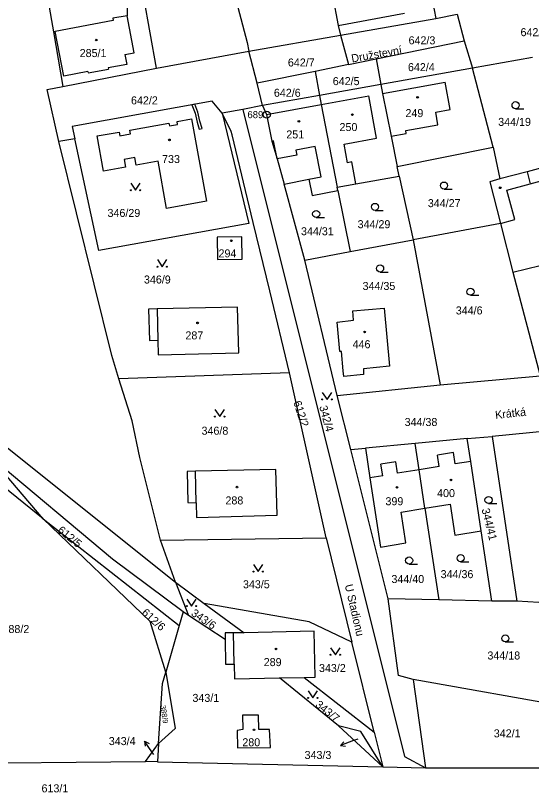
# Model space of a CAD drawing. Extents: x -758582 to -751794, y -998770 to -994350.
# Drawn here: x -756048.6 to -755939, y -995504.9 to -995339.9 of the extents above; entities that cross this region are included whole.
import ezdxf

# ---------------------------------------------------------------- set-up
doc = ezdxf.new("R2010")
doc.units = 0
for name, color, linetype in [('Hranice parcel', 7, 'Continuous'), ('Parcelní čísla', 7, 'Continuous'), ('Pop  PČ popisy', 7, 'Continuous'), ('Vnitřní kresba', 7, 'Continuous'), ('Věcná břemena k části', 7, 'Continuous'), ('Značky bodu BP', 7, 'Continuous'), ('Značky budov', 7, 'Continuous'), ('Značky kultur', 7, 'Continuous')]:
    doc.layers.add(name, color=color, linetype=linetype)

msp = doc.modelspace()

# ---------------------------------------------------------------- linework, layer by layer
at = {"layer": 'Hranice parcel'}
for p, q in [((-756018.71, -995351.04), (-756025.08, -995315.04)), ((-755959.34, -995340.51), (-755954.86, -995339.59)), ((-755954.86, -995339.59), (-755953.31, -995345.27)), ((-755979.58, -995344.08), (-755959.34, -995340.51)), ((-756040.6, -995343.32), (-756038.56, -995354.92)), ((-755999.06, -995347.44), (-755979.58, -995344.08)), ((-755979.58, -995344.08), (-755977.9, -995350.29)), ((-755972.03, -995349.09), (-755953.31, -995345.27)), ((-755953.31, -995345.27), (-755951.55, -995351.05)), ((-756018.71, -995351.04), (-755999.06, -995347.44)), ((-755997.28, -995354.25), (-755999.06, -995347.44)), ((-755977.9, -995350.29), (-755972.03, -995349.09)), ((-755972.03, -995349.09), (-755971.01, -995354.53)), ((-755938.83, -995348.79), (-755951.55, -995351.05)), ((-756038.56, -995354.92), (-756018.71, -995351.04)), ((-755985, -995351.74), (-755997.28, -995354.25)), ((-755977.9, -995350.29), (-755985, -995351.74)), ((-755985, -995351.74), (-755984.08, -995356.86)), ((-755951.55, -995351.05), (-755971.01, -995354.53)), ((-755947.19, -995367.83), (-755951.55, -995351.05)), ((-755996.16, -995359.02), (-755997.28, -995354.25)), ((-755971.01, -995354.53), (-755984.08, -995356.86)), ((-756006.88, -995358.06), (-756036.64, -995363.44)), ((-756004.76, -995360.64), (-756006.88, -995358.06)), ((-755984.08, -995356.86), (-755996.16, -995359.02)), ((-756000.35, -995359.81), (-756004.76, -995360.64)), ((-755996.16, -995359.02), (-756000.35, -995359.81)), ((-756004.76, -995360.64), (-755999.11, -995384.02)), ((-756036.64, -995363.44), (-756036.07, -995366.05)), ((-756036.07, -995366.05), (-756039.42, -995366.63)), ((-756030.95, -995389.82), (-756036.07, -995366.05)), ((-755967.56, -995371.96), (-755947.19, -995367.83)), ((-755947.19, -995367.83), (-755945.73, -995374.6)), ((-755967.16, -995373.98), (-755967.56, -995371.96)), ((-755967.16, -995373.98), (-755964.2, -995387.52)), ((-755987.18, -995391.82), (-755991.6, -995375.68)), ((-755980.19, -995377.02), (-755980.32, -995376.37)), ((-755980.19, -995377.02), (-755977.54, -995390.02)), ((-755999.11, -995384.02), (-756030.95, -995389.82)), ((-755945.62, -995384.05), (-755964.2, -995387.52)), ((-755945.62, -995384.05), (-755942.97, -995394.4)), ((-755977.54, -995390.02), (-755964.2, -995387.52)), ((-755964.2, -995387.52), (-755958.43, -995418.29)), ((-755987.18, -995391.82), (-755977.54, -995390.02)), ((-755980.31, -995420.59), (-755987.18, -995391.82)), ((-755942.97, -995394.4), (-755937.22, -995416.42)), ((-755990.43, -995415.78), (-756026.67, -995417.07)), ((-755982.69, -995450.85), (-755990.43, -995415.78)), ((-755958.43, -995418.29), (-755937.22, -995416.42)), ((-755980.31, -995420.59), (-755958.43, -995418.29)), ((-756064.11, -995420.68), (-756014.69, -995460.26)), ((-755977.43, -995432.09), (-755980.31, -995420.59)), ((-755929.72, -995427.54), (-755947.39, -995429.29)), ((-756042.77, -995446.79), (-756066.24, -995427.83)), ((-755952.69, -995429.73), (-755947.39, -995429.29)), ((-755947.39, -995429.29), (-755942.14, -995464.27)), ((-755963.78, -995430.8), (-755974.31, -995431.81)), ((-755952.69, -995429.73), (-755963.78, -995430.8)), ((-755977.43, -995432.09), (-755974.31, -995431.81)), ((-755969.45, -995463.77), (-755977.43, -995432.09)), ((-756042.77, -995446.79), (-756053.98, -995433.7)), ((-755961.69, -995444.53), (-755958.72, -995464.02)), ((-756042.77, -995446.79), (-756013.89, -995469.44)), ((-755947.43, -995464.28), (-755949.71, -995449.32)), ((-756017.87, -995451.33), (-755982.69, -995450.85)), ((-756014.69, -995460.26), (-756017.87, -995451.33)), ((-755982.69, -995450.85), (-755977.2, -995472.97)), ((-756014.69, -995460.26), (-756008.57, -995464.75)), ((-756014.69, -995460.26), (-756011.88, -995467.33)), ((-755958.72, -995464.02), (-755969.45, -995463.77)), ((-756008.57, -995464.75), (-756000.08, -995470.97)), ((-755947.43, -995464.28), (-755958.72, -995464.02)), ((-755942.14, -995464.27), (-755947.43, -995464.28)), ((-755924.21, -995465.35), (-755942.14, -995464.27)), ((-756013.06, -995466.56), (-756013.89, -995469.44)), ((-756011.88, -995467.33), (-756013.06, -995466.56)), ((-756004.08, -995472.41), (-756011.88, -995467.33)), ((-756013.89, -995469.44), (-756016.74, -995479.39)), ((-755972.46, -995492.09), (-755977.2, -995472.97)), ((-755992.54, -995480.58), (-755987.33, -995480.49)), ((-755980.04, -995490.76), (-755992.54, -995480.58)), ((-755987.33, -995480.49), (-755972.46, -995492.09)), ((-755964.16, -995480.95), (-755961.54, -995499.7)), ((-755970.63, -995499.45), (-755980.04, -995490.76)), ((-755972.46, -995492.09), (-755970.63, -995499.45)), ((-756021.03, -995498.34), (-756018.3, -995494.51)), ((-756018.3, -995494.51), (-756018.48, -995498.41)), ((-756018.48, -995498.41), (-756021.03, -995498.34)), ((-756018.48, -995498.41), (-755970.63, -995499.45)), ((-755970.63, -995499.45), (-755961.54, -995499.7)), ((-755961.54, -995499.7), (-755922.63, -995499.63))]:
    msp.add_line(p, q, dxfattribs=at)
for points in [[(-756029.41, -995294.31), (-756049.85, -995298.02), (-756045.34, -995316.28), (-756040.6, -995343.32)], [(-756007.01, -995316.86), (-755999.42, -995345.57), (-755999.06, -995347.44)], [(-755983.21, -995325.04), (-755981.28, -995335.57), (-755980.1, -995341.96), (-755979.58, -995344.08)], [(-755962.33, -995324.06), (-755960.86, -995332.14), (-755959.68, -995338.64), (-755959.34, -995340.51)], [(-756024.95, -995329.96), (-756024.91, -995339.91), (-756027.96, -995340.47), (-756027.87, -995340.96), (-756040.22, -995343.25), (-756040.6, -995343.32)], [(-756039.42, -995366.63), (-756041.92, -995355.6), (-756038.56, -995354.92)], [(-755971.01, -995354.53), (-755970.67, -995356.42), (-755968.86, -995365.49), (-755967.56, -995371.96)], [(-755984.08, -995356.86), (-755983.73, -995358.8), (-755980.32, -995376.37)], [(-756000.35, -995359.81), (-755966.03, -995497.26), (-755961.54, -995499.7)], [(-755996.16, -995359.02), (-755995.31, -995360.91), (-755994.18, -995366.59), (-755993.06, -995370.34), (-755991.6, -995375.68)], [(-755990.43, -995415.78), (-755994.59, -995398.38), (-755998.15, -995383.85), (-756002.6, -995365.24), (-756002.84, -995364.5), (-756004.76, -995360.64)], [(-756026.62, -995364.62), (-756026.47, -995365.44), (-756024.22, -995365.02), (-756024.37, -995364.21), (-756016.09, -995362.71), (-756015.96, -995363.33), (-756014.24, -995363.04), (-756014.34, -995362.4), (-756011.25, -995361.83), (-756008.1, -995379.31), (-756016.56, -995380.84), (-756018.37, -995370.82), (-756023.03, -995371.67), (-756023.33, -995370.03), (-756025.57, -995370.45), (-756025.27, -995372.06), (-756029.93, -995372.92), (-756031.27, -995365.46), (-756026.62, -995364.62)], [(-756026.67, -995417.07), (-756028.21, -995412.11), (-756039.42, -995366.63)], [(-755933.12, -995371.25), (-755934.52, -995371.62), (-755939.98, -995373.07), (-755945.73, -995374.6)], [(-755991.6, -995375.68), (-755986.35, -995374.64), (-755985.66, -995378.1), (-755980.19, -995377.02)], [(-755980.32, -995376.37), (-755976.38, -995375.65), (-755967.16, -995373.98)], [(-755945.73, -995374.6), (-755947.89, -995375.18), (-755945.62, -995384.05)], [(-756000.51, -995391.6), (-756000.59, -995386.87), (-756005.84, -995386.94), (-756005.75, -995391.72), (-756000.51, -995391.6)], [(-755942.97, -995394.4), (-755937.2, -995392.95), (-755932.45, -995391.73)], [(-756001.2, -995411.52), (-756001.47, -995401.81), (-756018.57, -995402.2), (-756020.37, -995402.24), (-756020.21, -995408.89), (-756018.41, -995408.85), (-756018.33, -995411.94), (-756001.2, -995411.52)], [(-755970.35, -995402.03), (-755969.19, -995414.38), (-755974.7, -995414.91), (-755974.69, -995416.15), (-755978.93, -995416.55), (-755979.02, -995415.38), (-755979.37, -995411.22), (-755979.77, -995411.25), (-755980.34, -995405.02), (-755976.84, -995404.59), (-755976.99, -995402.63), (-755970.35, -995402.03)], [(-756017.87, -995451.33), (-756022.21, -995433.78), (-756023.9, -995425.98), (-756026.67, -995417.07)], [(-755961.69, -995444.53), (-755962.93, -995436.38), (-755963.78, -995430.8)], [(-755949.71, -995449.32), (-755951.95, -995434.6), (-755952.69, -995429.73)], [(-755974.31, -995431.81), (-755973.37, -995438.07), (-755971.12, -995452.8), (-755965.7, -995451.92), (-755966.7, -995445.34), (-755961.69, -995444.53)], [(-756013.06, -995466.56), (-756028.01, -995455.35), (-756053.98, -995433.7)], [(-756010.39, -995436.68), (-756012.18, -995436.72), (-756012.06, -995443.34), (-756010.27, -995443.36), (-756010.2, -995446.48), (-755993.08, -995446.03), (-755993.34, -995436.31), (-756010.39, -995436.68)], [(-755961.69, -995444.53), (-755956.32, -995443.66), (-755955.32, -995450.23), (-755949.71, -995449.32)], [(-756016.74, -995479.39), (-756020.05, -995468.59), (-756042.77, -995446.79)], [(-755964.16, -995480.95), (-755967.26, -995480.08), (-755969.45, -995463.77)], [(-755977.2, -995472.97), (-755986.25, -995468.66), (-756008.57, -995464.75)], [(-756000.08, -995470.97), (-756002.31, -995471.02), (-756004.08, -995471.04), (-756004.08, -995472.41)], [(-755987.33, -995480.49), (-755984.99, -995480.45), (-755985.17, -995470.64), (-756000.08, -995470.97)], [(-756004.08, -995472.41), (-756004.07, -995477.65), (-756002.17, -995477.65), (-756002.11, -995480.79), (-755992.54, -995480.58)], [(-756016.74, -995479.39), (-756014.74, -995491.35), (-756018.3, -995494.51)], [(-756018.3, -995494.51), (-756017.43, -995481.8), (-756016.74, -995479.39)], [(-755924.33, -995487.02), (-755930.67, -995486.87), (-755964.16, -995480.95)], [(-756000.42, -995488.5), (-756000.36, -995491.54), (-756001.54, -995491.73), (-756001.46, -995495.43), (-755994.49, -995495.33), (-755994.7, -995491.57), (-755996.98, -995491.51), (-755997.01, -995488.47), (-756000.42, -995488.5)], [(-755970.63, -995499.45), (-755975.29, -995491.93), (-755980.04, -995490.76)], [(-756077.08, -995500.54), (-756065.33, -995498.79), (-756021.03, -995498.34)]]:
    msp.add_lwpolyline(points, dxfattribs=at)
at = {"layer": 'Pop  PČ popisy'}
for p, q in [((-755975.95, -995493.57), (-755976.83, -995493.9)), ((-756019.54, -995496.48), (-756021.22, -995493.99)), ((-756021.22, -995493.99), (-756020.24, -995494.54)), ((-756021.22, -995493.99), (-756021.07, -995495.1)), ((-755976.83, -995493.9), (-755979.63, -995494.97)), ((-755979.63, -995494.97), (-755978.88, -995494.15)), ((-755979.63, -995494.97), (-755978.52, -995495.08)), ((-756019.28, -995496.85), (-756019.54, -995496.48))]:
    msp.add_line(p, q, dxfattribs=at)
at = {"layer": 'Vnitřní kresba'}
for p, q in [((-756023.47, -995347.78), (-756024.91, -995339.91)), ((-755980.1, -995341.96), (-755966.03, -995339.37)), ((-756038.41, -995352.73), (-756040.22, -995343.25)), ((-756025.41, -995348.13), (-756023.47, -995347.78)), ((-756025.41, -995348.13), (-756025.02, -995350.26)), ((-756033.24, -995352.07), (-756028.87, -995351.25)), ((-756025.02, -995350.26), (-756028.93, -995350.98)), ((-756028.93, -995350.98), (-756028.87, -995351.25)), ((-756033.3, -995351.79), (-756038.41, -995352.73)), ((-756033.3, -995351.79), (-756033.24, -995352.07)), ((-755970.67, -995356.42), (-755957.39, -995354.01)), ((-755956.33, -995359.86), (-755957.39, -995354.01)), ((-755983.73, -995358.8), (-755973.59, -995356.95)), ((-755971.95, -995365.95), (-755973.59, -995356.95)), ((-755995.31, -995360.91), (-755983.73, -995358.8)), ((-755959.38, -995360.42), (-755956.33, -995359.86)), ((-755958.9, -995363.07), (-755959.38, -995360.42)), ((-755965.73, -995364.31), (-755958.9, -995363.07)), ((-755968.86, -995365.49), (-755965.63, -995364.9)), ((-755965.63, -995364.9), (-755965.73, -995364.31)), ((-755993.82, -995366.52), (-755994.18, -995366.59)), ((-755993.06, -995370.34), (-755993.82, -995366.52)), ((-755978.84, -995367.21), (-755971.95, -995365.95)), ((-755985.01, -995367.68), (-755989.12, -995368.49)), ((-755983.74, -995374.12), (-755985.01, -995367.68)), ((-755978.12, -995371.14), (-755978.84, -995367.21)), ((-755988.92, -995369.52), (-755993.06, -995370.34)), ((-755989.12, -995368.49), (-755988.92, -995369.52)), ((-755977.23, -995370.98), (-755978.12, -995371.14)), ((-755976.38, -995375.65), (-755977.23, -995370.98)), ((-755939.98, -995373.07), (-755939.3, -995375.62)), ((-755986.35, -995374.64), (-755983.74, -995374.12)), ((-755939.3, -995375.62), (-755933.84, -995374.16)), ((-755944.27, -995376.95), (-755939.3, -995375.62)), ((-755942.59, -995383.23), (-755944.27, -995376.95)), ((-755945.62, -995384.05), (-755942.59, -995383.23)), ((-756018.57, -995402.2), (-756018.41, -995408.85)), ((-755955.59, -995432.69), (-755959.01, -995433.25)), ((-755958.64, -995435.68), (-755959.01, -995433.25)), ((-755955.22, -995435.13), (-755955.59, -995432.69)), ((-755967.89, -995434.69), (-755971.01, -995435.2)), ((-755970.64, -995437.63), (-755971.01, -995435.2)), ((-755967.52, -995437.12), (-755967.89, -995434.69)), ((-755958.64, -995435.68), (-755962.93, -995436.38)), ((-755951.95, -995434.6), (-755955.22, -995435.13)), ((-756010.27, -995443.36), (-756010.39, -995436.68)), ((-755962.93, -995436.38), (-755967.52, -995437.12)), ((-755970.64, -995437.63), (-755973.37, -995438.07)), ((-756002.17, -995477.65), (-756002.31, -995471.02))]:
    msp.add_line(p, q, dxfattribs=at)
at = {"layer": 'Věcná břemena k části'}
msp.add_lwpolyline([(-756010.56, -995358.72), (-756011.16, -995358.83), (-756010.48, -995360.61), (-756010.05, -995362.5), (-756009.6, -995364.04), (-756009.02, -995363.88), (-756009.47, -995362.34), (-756009.91, -995360.43)], close=True, dxfattribs=at)
at = {"layer": 'Značky bodu BP'}
for radius in [0.75, 0.03]:
    msp.add_circle((-755995.27, -995360.93), radius, dxfattribs=at)
at = {"layer": 'Značky budov'}
for centre in [(-756031.48, -995345.08), (-755963.25, -995357.24), (-755977.08, -995360.92), (-755988.45, -995362.36), (-756015.95, -995366.29), (-755945.69, -995376.46), (-756002.81, -995387.72), (-756009.97, -995405.17), (-755974.48, -995407.1), (-755956.15, -995438.53), (-756001.58, -995440.05), (-755967.6, -995440.11), (-755993.3, -995474.43), (-755998, -995491.61)]:
    msp.add_circle(centre, 0.175, dxfattribs=at)
at = {"layer": 'Značky kultur'}
for p, q in [((-755942.42, -995359.67), (-755940.67, -995359.67)), ((-755957.62, -995376.74), (-755955.87, -995376.74)), ((-755972.28, -995381.27), (-755970.53, -995381.27)), ((-755984.78, -995382.78), (-755983.03, -995382.78)), ((-755971.2, -995394.36), (-755969.45, -995394.36)), ((-755952, -995399.3), (-755950.25, -995399.3)), ((-755948.17, -995443.54), (-755946.42, -995443.54)), ((-755965.03, -995456.39), (-755963.28, -995456.39)), ((-755954.1, -995455.89), (-755952.35, -995455.89)), ((-755944.6, -995472.94), (-755942.85, -995472.94))]:
    msp.add_line(p, q, dxfattribs=at)
for points in [[(-756024.14, -995375.48), (-756023.14, -995376.98), (-756022.14, -995375.48)], [(-756018.5, -995391.73), (-756017.5, -995393.23), (-756016.5, -995391.73)], [(-755983.47, -995419.92), (-755982.47, -995421.42), (-755981.47, -995419.92)], [(-756006.27, -995423.56), (-756005.27, -995425.06), (-756004.27, -995423.56)], [(-755998.09, -995456.5), (-755997.09, -995458), (-755996.09, -995456.5)], [(-756012.24, -995463.82), (-756011.24, -995465.32), (-756010.24, -995463.82)], [(-755981.7, -995474.16), (-755980.7, -995475.66), (-755979.7, -995474.16)], [(-755986.49, -995483.34), (-755985.49, -995484.84), (-755984.49, -995483.34)]]:
    msp.add_lwpolyline(points, dxfattribs=at)
for centre, radius in [((-755942.42, -995358.92), 0.75), ((-755957.62, -995375.99), 0.75), ((-756024.14, -995376.98), 0.1), ((-756022.14, -995376.98), 0.1), ((-755972.28, -995380.52), 0.75), ((-755984.78, -995382.03), 0.75), ((-755971.2, -995393.61), 0.75), ((-756018.5, -995393.23), 0.1), ((-756016.5, -995393.23), 0.1), ((-755952, -995398.55), 0.75), ((-755983.47, -995421.42), 0.1), ((-755981.47, -995421.42), 0.1), ((-756006.27, -995425.06), 0.1), ((-756004.27, -995425.06), 0.1), ((-755948.17, -995442.79), 0.75), ((-755965.03, -995455.64), 0.75), ((-755954.1, -995455.14), 0.75), ((-755998.09, -995458), 0.1), ((-755996.09, -995458), 0.1), ((-756012.24, -995465.32), 0.1), ((-756010.24, -995465.32), 0.1), ((-755944.6, -995472.19), 0.75), ((-755981.7, -995475.66), 0.1), ((-755979.7, -995475.66), 0.1), ((-755986.49, -995484.84), 0.1), ((-755984.49, -995484.84), 0.1)]:
    msp.add_circle(centre, radius, dxfattribs=at)

# ---------------------------------------------------------------- texts
at = {"layer": 'Parcelní čísla'}
for s, p in [('642/1', (-755941.37, -995344.26)), ('642/3', (-755965.15, -995345.99)), ('285/1', (-756035.02, -995348.7)), ('642/7', (-755990.79, -995350.7)), ('642/4', (-755965.28, -995351.69)), ('642/5', (-755981.25, -995354.66)), ('642/6', (-755993.76, -995357.14)), ('642/2', (-756024.11, -995358.75)), ('249', (-755965.81, -995361.45)), ('344/19', (-755946.11, -995363.32)), ('250', (-755979.82, -995364.42)), ('251', (-755991.12, -995365.98)), ('733', (-756017.51, -995371.21)), ('344/27', (-755961.06, -995380.58)), ('346/29', (-756029.1, -995382.66)), ('344/29', (-755975.97, -995385.05)), ('344/31', (-755988, -995386.55)), ('294', (-756005.52, -995391.25)), ('346/9', (-756021.36, -995396.8)), ('344/35', (-755974.92, -995398.17)), ('344/6', (-755955.12, -995403.37)), ('287', (-756012.55, -995408.67)), ('446', (-755977.04, -995410.55)), ('344/38', (-755965.99, -995427.07)), ('346/8', (-756009.13, -995428.92)), ('400', (-755959.09, -995442.17)), ('288', (-756004.05, -995443.73)), ('399', (-755970.06, -995443.9)), ('344/40', (-755968.79, -995460.43)), ('344/36', (-755958.34, -995459.39)), ('343/5', (-756000.33, -995461.54)), ('388/2', (-756051.41, -995471.05)), ('344/18', (-755948.4, -995476.67)), ('289', (-755995.92, -995478.07)), ('343/2', (-755984.18, -995479.33)), ('343/1', (-756011.06, -995485.68)), ('342/1', (-755947.05, -995493.21)), ('343/4', (-756028.83, -995494.85)), ('280', (-756000.46, -995495.1)), ('343/3', (-755987.24, -995497.8)), ('613/1', (-756043.12, -995504.89))]:
    msp.add_text(s, height=1.7, dxfattribs=at).set_placement(p)
for s, height, rotation, p in [('612/2', 1.7, 288, (-755989.66, -995422.02)), ('342/4', 1.7, 285, (-755984.14, -995422.94)), ('344/41', 1.7, 284, (-755949.65, -995444.77)), ('612/5', 1.7, 321, (-756039.85, -995449.48)), ('612/6', 1.7, 318, (-756021.98, -995466.92)), ('343/6', 1.7, 326, (-756011.49, -995467.21)), ('388/9', 1.14, 278, (-756017.86, -995486.43)), ('343/7', 1.7, 321, (-755985.1, -995486.53))]:
    msp.add_text(s, height=height, rotation=rotation, dxfattribs=at).set_placement(p)
at = {"layer": 'Pop  PČ popisy'}
for s, rotation, p in [('Družstevní', 10, (-755977.15, -995349.87)), ('Krátká', 6, (-755946.67, -995425.57)), ('U Stadionu', 283, (-755978.71, -995460.89))]:
    msp.add_text(s, height=1.7, rotation=rotation, dxfattribs=at).set_placement(p)
at = {"layer": 'Značky bodu BP'}
msp.add_text('689', height=1.5, dxfattribs=at).set_placement((-755999.37, -995361.68))

doc.saveas('drawing.dxf')
